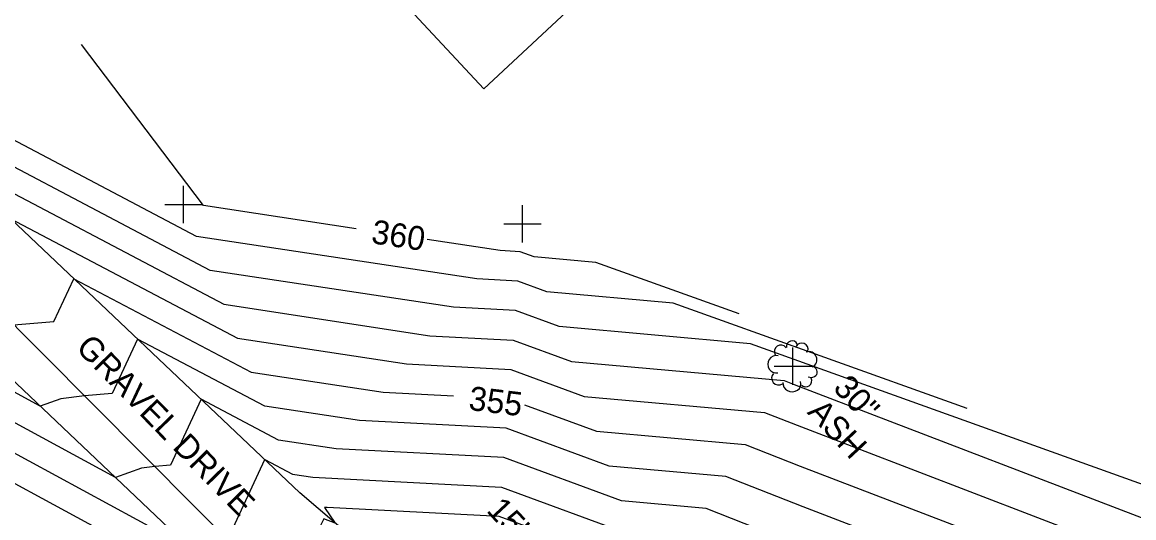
# Model space of a CAD drawing. Extents: x 487096 to 489566, y 221939 to 224454.
# Drawn here: x 487821.4 to 487970.1, y 223834.5 to 223900.8 of the extents above; entities that cross this region are included whole.
import ezdxf

# ---------------------------------------------------------------- set-up
doc = ezdxf.new("R2010")
doc.units = 0
for name, color, linetype in [('SV_BKLN_EARTH_TOP', 7, 'Continuous'), ('SV_CTRL_TIE_BOX', 7, 'Continuous'), ('SV_ROAD_GRAVRD', 7, 'Continuous'), ('SV_ROAD_ROAD_TX', 7, 'Continuous'), ('SV_SURF_INDEX_CONTOUR', 7, 'Continuous'), ('SV_SURF_INTER_CONTOUR', 7, 'Continuous'), ('SV_SURF_SPOT', 7, 'Continuous'), ('SV_TREE_TREEVEG', 7, 'Continuous'), ('SV_TREE_TREEVEG_TX', 7, 'Continuous')]:
    doc.layers.add(name, color=color, linetype=linetype)

msp = doc.modelspace()

# ---------------------------------------------------------------- linework, layer by layer
at = {"layer": 'SV_BKLN_EARTH_TOP'}
msp.add_lwpolyline([(487899.13, 223790.17), (487849.86, 223824.73), (487785.15, 223886.13)], dxfattribs=at)
at = {"layer": 'SV_CTRL_TIE_BOX'}
msp.add_lwpolyline([(487801.33, 223979.69), (487883.17, 223891.93), (487941.68, 223946.48), (487859.84, 224034.25)], close=True, dxfattribs=at)
at = {"layer": 'SV_ROAD_GRAVRD'}
for points in [[(487935.77, 223771.81), (487858.55, 223837.83), (487796.63, 223896.51)], [(487909.17, 223782.99), (487851.39, 223829), (487789.82, 223890.99)]]:
    msp.add_lwpolyline(points, dxfattribs=at)
at = {"layer": 'SV_SURF_INDEX_CONTOUR'}
for points in [[(487866.09, 223873.17), (487845.64, 223876.28), (487829.32, 223897.84)], [(487917.32, 223861.79), (487898.14, 223868.67), (487889.9, 223869.41), (487888.02, 223870.1), (487885.34, 223870.25), (487875.59, 223871.73)], [(487801.55, 223865.62), (487813.73, 223859.01), (487815.76, 223859.73), (487820.29, 223860.31), (487825.64, 223860.75), (487828.31, 223866.5), (487852.04, 223853.98), (487869.68, 223851.29), (487879.08, 223850.8)], [(487888.61, 223849.63), (487898.24, 223846.09), (487918.12, 223844.3), (487925.47, 223841.41), (487966.91, 223825.5), (487969.53, 223822.73)]]:
    msp.add_lwpolyline(points, dxfattribs=at)
at = {"layer": 'SV_SURF_INTER_CONTOUR'}
for points in [[(487947.85, 223849.1), (487908.48, 223863.23), (487891.57, 223864.75), (487887.71, 223866.17), (487882.21, 223866.46), (487844.7, 223872.16), (487807.27, 223891.91), (487769.81, 223921.23), (487768.69, 223922.01), (487768.47, 223922.17), (487768.22, 223922.59)], [(487978.37, 223836.41), (487918.82, 223857.78), (487893.24, 223860.08), (487887.4, 223862.23), (487879.08, 223862.67), (487846.53, 223867.61), (487802.76, 223890.71), (487802.25, 223889.59), (487792.04, 223888.75), (487787.06, 223888.11), (487782.82, 223891.17), (487767.31, 223917.05)], [(487766.39, 223911.52), (487783.04, 223883.73), (487784.38, 223883.05), (487784.62, 223882.94), (487784.86, 223882.82), (487785.1, 223882.71), (487786.65, 223881.72), (487787.88, 223881.22), (487793.59, 223878.12), (487794.19, 223878.34), (487801.45, 223879.27), (487810.04, 223879.98), (487811.28, 223882.64), (487848.37, 223863.07), (487875.94, 223858.87), (487887.09, 223858.29), (487894.9, 223855.42), (487923.34, 223852.86), (487924.69, 223852.33), (487977.96, 223831.88)], [(487765.48, 223905.98), (487780.53, 223880.87), (487783.45, 223879.37), (487783.98, 223879.12), (487784.51, 223878.88), (487785.05, 223878.63), (487788.44, 223876.46), (487791.14, 223875.36), (487803.66, 223868.56), (487804.97, 223869.03), (487810.87, 223869.79), (487817.84, 223870.37), (487819.79, 223874.57), (487850.2, 223858.52), (487872.81, 223855.08), (487886.78, 223854.35), (487896.57, 223850.75), (487920.73, 223848.58), (487925.08, 223846.87), (487972.43, 223828.69)], [(487978.17, 223816.6), (487965.1, 223818.39), (487961.38, 223822.32), (487925.87, 223835.95), (487915.52, 223840.02), (487899.91, 223841.42), (487886.16, 223846.48), (487866.54, 223847.5), (487853.87, 223849.43), (487836.82, 223858.42), (487833.44, 223851.14), (487829.71, 223850.83), (487826.55, 223850.42), (487823.81, 223849.45), (487797.65, 223863.65), (487792.03, 223865.94), (487784.93, 223870.47), (487783.82, 223870.99), (487782.71, 223871.5), (487781.61, 223872.02), (487775.5, 223875.15), (487763.66, 223894.91)], [(487976.99, 223811.93), (487960.54, 223814.18), (487955.86, 223819.13), (487926.26, 223830.49), (487912.91, 223835.74), (487901.57, 223836.76), (487885.85, 223842.54), (487863.41, 223843.71), (487855.7, 223844.89), (487845.34, 223850.35), (487841.23, 223841.53), (487839.12, 223841.35), (487837.34, 223841.12), (487833.88, 223839.89), (487800.91, 223857.79), (487793.82, 223860.68), (487784.87, 223866.39), (487783.47, 223867.04), (487782.07, 223867.69), (487780.68, 223868.34), (487772.98, 223872.29), (487762.74, 223889.37)], [(487761.83, 223883.84), (487770.46, 223869.43), (487779.76, 223864.67), (487781.44, 223863.88), (487783.12, 223863.1), (487784.82, 223862.31), (487795.61, 223855.42), (487804.16, 223851.94), (487843.95, 223830.33), (487848.13, 223831.82), (487848.54, 223831.87), (487849.03, 223831.91), (487853.85, 223842.28), (487857.54, 223840.34), (487860.28, 223839.92), (487885.54, 223838.6), (487903.24, 223832.09), (487910.31, 223831.46), (487926.65, 223825.04), (487950.33, 223815.94), (487955.98, 223809.98), (487975.82, 223807.26)], [(487974.64, 223802.59), (487951.42, 223805.78), (487944.81, 223812.76), (487927.04, 223819.58), (487907.7, 223827.17), (487904.91, 223827.42), (487885.23, 223834.66), (487862.21, 223835.87), (487861.83, 223835.88), (487863.29, 223833.78), (487861.75, 223834.36), (487856.88, 223824.63), (487856.37, 223824.95), (487853.05, 223822.49), (487851.29, 223822.67), (487849.89, 223823.46), (487849.65, 223823.55), (487849.4, 223823.65), (487849.15, 223823.74), (487848.9, 223823.85), (487848.66, 223823.95), (487846.89, 223824.65), (487807.42, 223846.08)]]:
    msp.add_lwpolyline(points, dxfattribs=at)
at = {"layer": 'SV_SURF_SPOT'}
for p, q in [((487842.97, 223873.93), (487842.97, 223878.93)), ((487840.47, 223876.43), (487845.47, 223876.43)), ((487842.97, 223876.43), (487842.97, 223876.43)), ((487888.32, 223871.34), (487888.32, 223876.35)), ((487885.82, 223873.85), (487890.82, 223873.85)), ((487888.32, 223873.85), (487888.32, 223873.85)), ((487924.51, 223852.29), (487924.51, 223857.29)), ((487922.01, 223854.79), (487927.01, 223854.79)), ((487924.51, 223854.79), (487924.51, 223854.79))]:
    msp.add_line(p, q, dxfattribs=at)
at = {"layer": 'SV_TREE_TREEVEG'}
msp.add_line((487924.51, 223854.79), (487924.51, 223854.79), dxfattribs=at)
for centre, radius, start, end in [((487924.4, 223857.44), 0.75, 23.2911, 192.3579), ((487922.9, 223856.75), 0.874, 35.9933, 211.459), ((487925.71, 223857.03), 0.85, 345.5308, 152.7093), ((487926.67, 223855.67), 1.06, 294.1859, 111.1082), ((487922.31, 223855.04), 1.17, 79.3292, 279.9889), ((487922.59, 223853.19), 0.922, 137.0157, 304.5501)]:
    msp.add_arc(centre, radius, start, end, dxfattribs=at)
for centre, major_axis, ratio, start_param, end_param in [((487926.96, 223854.02), (0.822, -0.013), 0.901056, 4.216583, 7.444153), ((487924.38, 223852.46), (-1.2, 0.16), 0.902156, 0, 3.5401), ((487926.23, 223852.82), (0.08, -0.798), 0.999752, 5.391582, 8.241319)]:
    msp.add_ellipse(centre, major_axis=major_axis, ratio=ratio, start_param=start_param, end_param=end_param, dxfattribs=at)

# ---------------------------------------------------------------- texts
at = {"layer": 'SV_ROAD_ROAD_TX'}
msp.add_text('GRAVEL DRIVE', height=3.2, rotation=314.2985, dxfattribs=at).set_placement((487828.43, 223857.12))
at = {"layer": 'SV_SURF_INDEX_CONTOUR'}
for s, rotation, p in [('360', 351.3568, (487867.98, 223871.27)), ('355', 353.005, (487881.02, 223848.95))]:
    msp.add_text(s, height=3.2, rotation=rotation, dxfattribs=at).set_placement(p)
at = {"layer": 'SV_TREE_TREEVEG_TX'}
for s, p in [('30"', (487929.76, 223851.75)), ('ASH', (487926.33, 223848.54)), ('15"', (487883.39, 223835.4))]:
    msp.add_text(s, height=3.2, rotation=313.0386, dxfattribs=at).set_placement(p)

doc.saveas('drawing.dxf')
